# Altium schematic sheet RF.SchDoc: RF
size A4; Date: Not used; ApprovedBy: Not used; CheckedBy: Not used; Author: Not used; CompanyName: STMicroelectronics; DrawnBy: Not used; Engineer: Not used; Organization: Not used; Address1: Not used; Address2: Not used; Address3: Not used; Address4: Not used; DocumentNumber: Not used; Revision: Not used; SheetNumber: 4; SheetTotal: 6
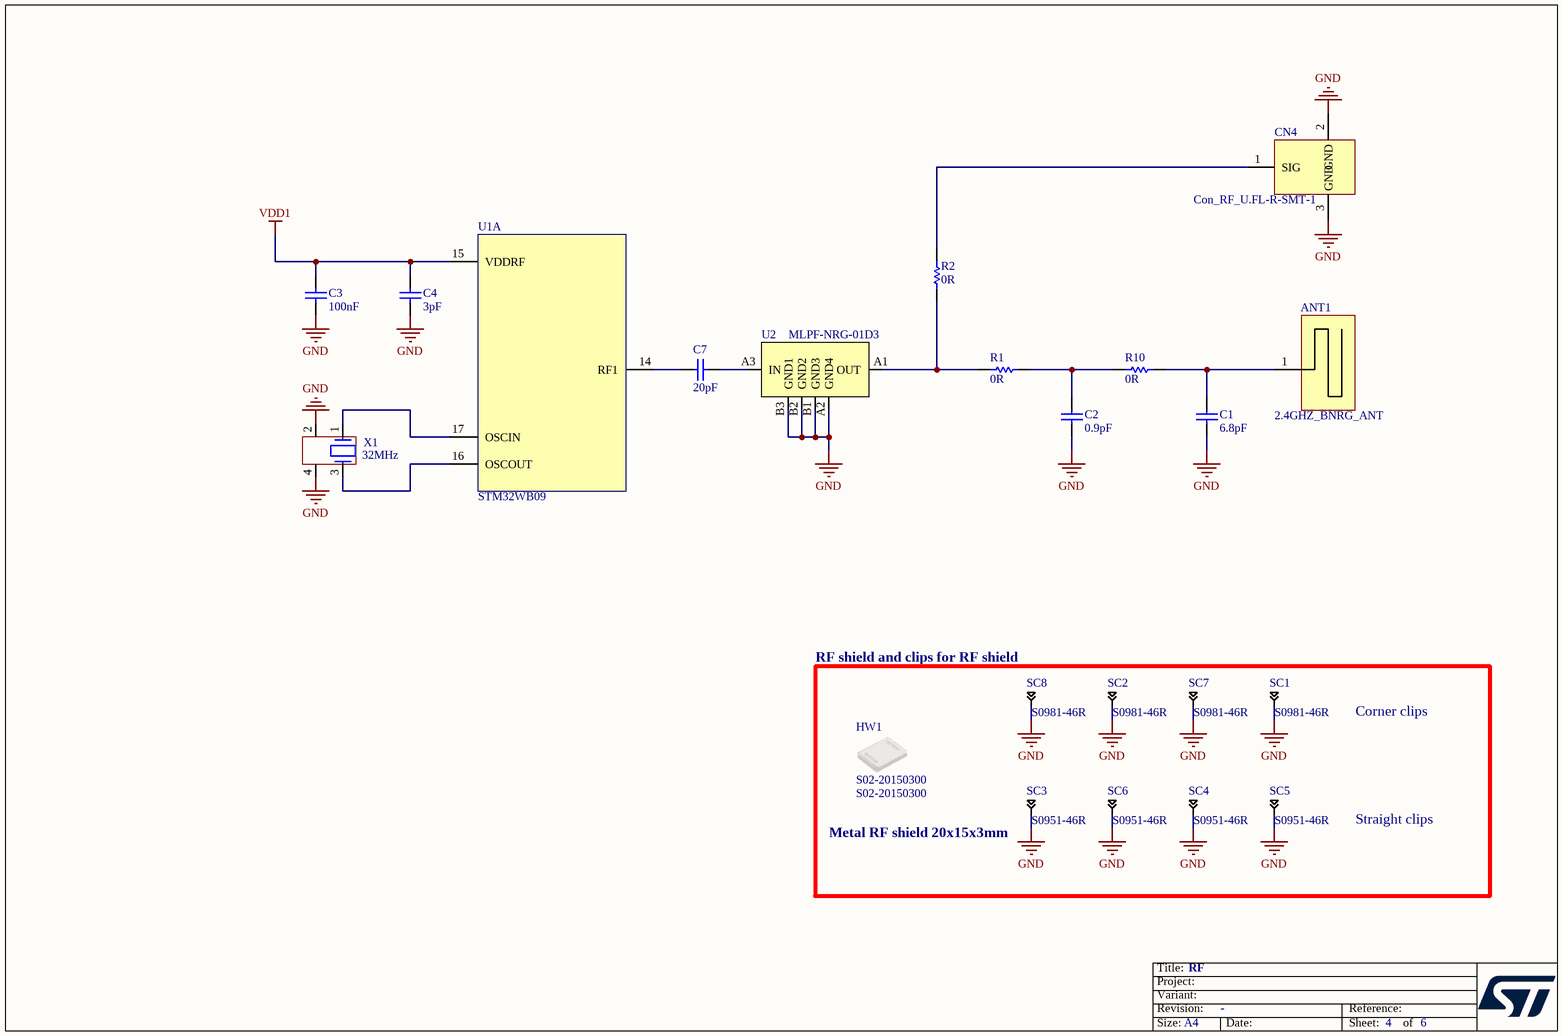
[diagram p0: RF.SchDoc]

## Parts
ANT1  value 2.4GHZ_BNRG_ANT  [ANT_BT_BNRG_2P4GHZ_MB2032]  (hidden comment: 2.4GHz_BT_ANT)  (no BOM)
C1  value 6.8pF  [C0402]  (hidden comment: Capacitor)
C2  value 0.9pF  [C0402_MURATA_GJM155_H0P5]  (hidden comment: Capacitor)
C3  value 100nF  [C0402]  (hidden comment: Capacitor)
C4  value 3pF  [C0402]  (hidden comment: Capacitor)
C7  value 20pF  [C0201_H0P3]  (hidden comment: Capacitor)
CN4  value Con_RF_U.FL-R-SMT-1  [CON_HRS_U.FL-R-SMT-1]  (hidden comment: U.FL-R-SMT-1)
HW1  S02-20150300  [SHIELD_HARWIN_S02-20150300_15X20_H3]
R1  value 0R  [R0402]  (hidden comment: Resistor)
R2  value 0R  [r0402]  (hidden comment: Resistor)
R10  value 0R  [R0402]  (hidden comment: Resistor)
SC1  value S0981-46R  [CLIP_HARWIN_S0981-46R]  (hidden comment: Shield-clip_S0951-46R)
SC2  value S0981-46R  [CLIP_HARWIN_S0981-46R]  (hidden comment: Shield-clip_S0951-46R)
SC3  value S0951-46R  [CLIP_HARWIN_S0951-46R]  (hidden comment: Shield-clip_S0951-46R)
SC4  value S0951-46R  [CLIP_HARWIN_S0951-46R]  (hidden comment: Shield-clip_S0951-46R)
SC5  value S0951-46R  [CLIP_HARWIN_S0951-46R]  (hidden comment: Shield-clip_S0951-46R)
SC6  value S0951-46R  [CLIP_HARWIN_S0951-46R]  (hidden comment: Shield-clip_S0951-46R)
SC7  value S0981-46R  [CLIP_HARWIN_S0981-46R]  (hidden comment: Shield-clip_S0951-46R)
SC8  value S0981-46R  [CLIP_HARWIN_S0981-46R]  (hidden comment: Shield-clip_S0951-46R)
U1  STM32WB09  [ICC_QFN32-EPAD_5X5_P050]  (part A of 5)
U2  value MLPF-NRG-01D3  [ICC_CSPG_6BUMPS_1X1P60_P050-P0577]  (hidden comment: MLPF-WB55-01E3)
X1  value 32MHz  [CRY_NX2016SA_4P]  (hidden comment: XTAL_4_PINS)

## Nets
GND: C1.1 C2.1 C3.1 C4.1 CN4.2(GND) CN4.3(GND) SC1.1 SC2.1 SC3.1 SC4.1 SC5.1 SC6.1 SC7.1 SC8.1 U2.A2(GND4) U2.B1(GND3) U2.B2(GND2) U2.B3(GND1) X1.2 X1.4
VDD1: C3.2 C4.2 U1.15(VDDRF)
NetANT1_1: ANT1.1 C1.2 R10.2
NetC2_2: C2.2 R1.2 R10.1
NetC7_1: C7.1 U1.14(RF1)
NetC7_2: C7.2 U2.A3(IN)
NetCN4_1: CN4.1(SIG) R2.2
NetR1_1: R1.1 R2.1 U2.A1(OUT)
NetU1_16: U1.16(OSCOUT) X1.3
NetU1_17: U1.17(OSCIN) X1.1

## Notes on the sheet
- (near SC8) RF shield and clips for RF shield
- Corner clips
- (near SC3) Metal RF shield 20x15x3mm
- Straight clips

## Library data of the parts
ANT1 = MCD-03495: 2.4 GHZ Bluetooth BNRG PCB antenna; Part_Type: Misc; Part_Preference: Recommended; ShowFields: YES; ID: 5611; Component_Country_Of_Origin: Unknown
C1 = MCD-03452: Capacitor, MLCC, 6.8pF, 50V, C0G, +/-0.05pF, 0402, T=0.5mm; Part_Preference: Recommended; Manufacturer: MURATA; Manufacturer_Part_Number: GJM1555C1H6R8WB01; Order_Code_RS: 3243259RL; ShowFields: YES; ID: 5568; Component_Country_Of_Origin: Japan, Singapore
C2 = MCD-04106: Capacitor, MLCC, 0.9pF, 50V, COG, +/-0.05pF, 0402, T=0.5mm; Part_Preference: Recommended; Manufacturer: MURATA; Manufacturer_Part_Number: GJM1555C1HR90WB01; Order_Code_RS: 185-3185; ShowFields: YES; ID: 6222
C3 = MCD-03442: Capacitor, MLCC, 100nF, ±10%, X7R, 25V, 0402, T=0.5mm; Part_Preference: Recommended; Manufacturer: MURATA; Manufacturer_Part_Number: GRM155R71E104KE14D; Order_Code_RS: NA; ShowFields: YES; ID: 5558; Component_Country_Of_Origin: China, Japan, Philippines, Singapore
C4 = MCD-03898: Capacitor, C0G, 3 pF, 50V, NPO, ±0.1pF, 0402, T=0.5mm; Part_Preference: Recommended; Manufacturer: WALSIN TECHNOLOGY CORPORATION; Manufacturer_Part_Number: 0402N3R0B500CT; Order_Code_RS: NA; ShowFields: YES; ID: 6014
C7 = MCD-03543: Capacitor, MLCC, 20pF, 25V, COG, +/-2%, 0201, T=0.33mm; Part_Preference: Recommended; Manufacturer: MURATA; Manufacturer_Part_Number: GJM0335C1E200GB01; ShowFields: YES; ID: 5659; Component_Country_Of_Origin: Japan, Singapore
CN4 = MCD-01583: Connector_RF, 0Hz to 6GHz, 50R, VR, SMD, T= 1.25mm; BMS_Part_Number: 9187005; Part_Preference: Recommended; Manufacturer: HIROSE; Order_Code_RS: 557-981; Component_Country_Of_Origin: Japan, Malaysia; ShowFields: YES; ID: 3683
HW1 = MCD-03126: RFI shield can, 20x15x3mm; Part_Type: Misc; Part_Preference: Recommended; Manufacturer: HARWIN; Order_Code_RS: 161-3687; Component_Country_Of_Origin: UK°; ShowFields: YES; ID: 5242
R1 R2 R10 = MCD-00052: Resistor, 0R, 0402, +/-5%, 1/16W; Part_Preference: Recommended; Manufacturer: YAGEO; Manufacturer_Part_Number: RC0402JR-070RL; Order_Code_RS: 9232516RL; Component_Country_Of_Origin: China; ShowFields: YES; ID: 2540
SC1 SC2 SC7 SC8 = MCD-02164: shield clip Harwin S0981-46R to fix RF shielded cavity - SMT RFI Shield Clip, Corner (T+R); Part_Type: Mechanical; Part_Preference: Recommended; Order_Code_RS: 161-3702; Component_Country_Of_Origin: South Korea; ShowFields: YES; ID: 4264
SC3-SC6 = MCD-01587: shield clip Harwin S0951-46R to fix RF shielded cavity; Part_Type: Mechanical; Part_Preference: Recommended; Component_Country_Of_Origin: South Korea; ShowFields: YES; ID: 3687
U1 = MCD-03444: Bluetooth® Low Energy wireless SoC; Part_Type: IC; Part_Preference: Recommended; Manufacturer: STMICROELECTRONICS; Component_Country_Of_Origin: Unknown; ShowFields: YES; ID: 5560
U2 = MCD-03490: 2.4 GHz low pass filter matched to BLUENRG-LP-LPS; Part_Type: IC; Part_Preference: Recommended; Manufacturer: STMICROELECTRONICS; ShowFields: YES; ID: 5606; Component_Country_Of_Origin: China
X1 = MCD-01446: Crystal, 32MHz, 8pF, +/-10ppm, 60R, 2x1.6mm; BMS_Part_Number: 9157042; Part_Type: Crystal_Osc; Part_Preference: Recommended; Manufacturer: NDK; Manufacturer_Part_Number: NX2016SA-32MHZ-EXS00A-CS06654; Component_Country_Of_Origin: Unknown; ShowFields: YES; ID: 3546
